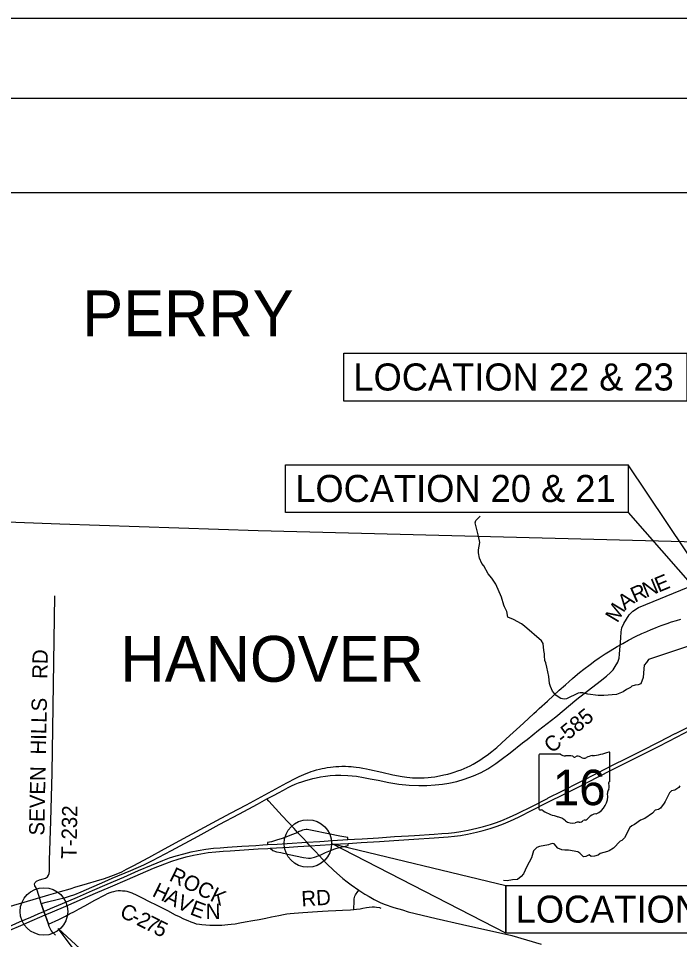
# Model space of a CAD drawing. Extents: x 0 to 34, y 0 to 22.
# Drawn here: x 10.63 to 14.77, y 16.22 to 22 of the extents above; entities that cross this region are included whole.
import ezdxf

# ---------------------------------------------------------------- set-up
doc = ezdxf.new("R2010")
doc.units = 0
for name, color, linetype in [('BR_P_Gen_Text', 7, 'Continuous'), ('Default', 7, 'Continuous'), ('GM_X_County_Road', 7, 'Continuous'), ('GM_X_County_Road_Text', 7, 'Continuous'), ('GM_X_Interchange_Ramps', 7, 'Continuous'), ('GM_X_Minor_River', 7, 'Continuous'), ('GM_X_Rail_Line', 7, 'Continuous'), ('GM_X_State_Route', 7, 'Continuous'), ('GM_X_State_Shield', 7, 'Continuous'), ('GM_X_Township', 7, 'Continuous'), ('GM_X_Township_Road', 7, 'Continuous'), ('GM_X_Township_Road_Text', 7, 'Continuous'), ('GM_X_Township_Text', 7, 'Continuous'), ('SH_Border', 7, 'Continuous'), ('SH_Cut_Line', 7, 'Continuous'), ('SH_Text', 7, 'Continuous')]:
    doc.layers.add(name, color=color, linetype=linetype)

msp = doc.modelspace()

# ---------------------------------------------------------------- linework, layer by layer
at = {"layer": 'BR_P_Gen_Text'}
for points in [[(12.6681, 19.8992), (14.8201, 19.8992), (14.8201, 19.5989), (12.6681, 19.5989)], [(12.3032, 19.1999), (14.4514, 19.1999), (14.4514, 18.8997), (12.3032, 18.8997)], [(14.4514, 19.1999), (14.4514, 18.8997), (15.3028, 17.9312)], [(13.6851, 16.5609), (13.6851, 16.2607), (12.5922, 16.8244)], [(13.6851, 16.5609), (15.8312, 16.5609), (15.8312, 16.2607), (13.6851, 16.2607)], [(11.6138, 15.6114), (11.6138, 15.3112), (10.8775, 16.2902)]]:
    msp.add_lwpolyline(points, close=True, dxfattribs=at)
at = {"layer": 'Default'}
for centre in [(12.4433, 16.8244), (10.7881, 16.398)]:
    msp.add_circle(centre, 0.149, dxfattribs=at)
at = {"layer": 'GM_X_County_Road'}
msp.add_line((10.7963, 16.3759), (10.8163, 16.3184), dxfattribs=at)
for points in [[(11.4683, 16.7168), (11.5872, 16.7801), (11.7557, 16.8707), (11.8872, 16.9424), (12.0134, 17.0104), (12.1272, 17.0718), (12.1864, 17.1037), (12.231, 17.1282), (12.2588, 17.1423), (12.2899, 17.1594), (12.319, 17.1748), (12.3404, 17.185), (12.3639, 17.1957), (12.3852, 17.2043), (12.4049, 17.2111), (12.4296, 17.2192), (12.4529, 17.2261), (12.4732, 17.232), (12.495, 17.2367), (12.5224, 17.242), (12.5531, 17.2469), (12.5823, 17.2502), (12.6156, 17.252), (12.649, 17.253), (12.6947, 17.2516), (12.7489, 17.2462), (12.7921, 17.2389), (12.8343, 17.2304), (12.8836, 17.2205), (12.9513, 17.207), (13.0141, 17.1961), (13.0787, 17.1899), (13.1393, 17.1875), (13.1883, 17.1886), (13.2418, 17.1916), (13.2864, 17.1969), (13.3266, 17.2032), (13.3769, 17.2136), (13.4237, 17.2271), (13.4823, 17.248), (13.5289, 17.2693), (13.5726, 17.2929), (13.6222, 17.3251), (13.6561, 17.3506), (13.7115, 17.3938), (13.7899, 17.4552), (13.8178, 17.4761), (13.8899, 17.5341), (13.998, 17.619), (14.1297, 17.7296), (14.2764, 17.842), (14.3148, 17.8733), (14.3402, 17.8963), (14.3576, 17.914), (14.3705, 17.9335), (14.3858, 17.9627), (14.3942, 17.9878), (14.3976, 18.0121), (14.406, 18.1138), (14.4078, 18.153), (14.4121, 18.1764), (14.4247, 18.2053), (14.4572, 18.2595), (14.4802, 18.2806), (14.5173, 18.3053), (14.8268, 18.432)], [(12.513, 16.7489), (12.49, 16.773), (12.4561, 16.8103), (12.4359, 16.8319), (12.413, 16.8571), (12.3788, 16.8938), (12.3568, 16.9179), (12.2812, 16.9986), (12.1979, 17.0898), (12.1864, 17.1037)], [(10.7699, 16.4471), (10.8105, 16.4578), (10.8709, 16.4731), (10.9224, 16.4864), (10.9479, 16.4933), (10.9818, 16.5046), (11.022, 16.5206), (11.1705, 16.5851), (11.2167, 16.6057), (11.3322, 16.6543), (11.4135, 16.6899), (11.4683, 16.7168)], [(10.8163, 16.3184), (10.8819, 16.3481), (10.9023, 16.3584), (10.9239, 16.369), (10.9485, 16.3827), (10.9788, 16.3986), (11.009, 16.4149), (11.0439, 16.4339), (11.1077, 16.4677), (11.1712, 16.5023), (11.1871, 16.51), (11.2028, 16.5169), (11.2151, 16.5216), (11.2254, 16.5239), (11.2403, 16.5269), (11.2533, 16.5286), (11.2676, 16.5289), (11.2802, 16.5282), (11.2968, 16.5262), (11.3081, 16.5246), (11.3204, 16.5213), (11.339, 16.5149), (11.3703, 16.4997), (11.4048, 16.4824), (11.4477, 16.4604), (11.4919, 16.4388), (11.562, 16.4033), (11.6115, 16.377), (11.6365, 16.3654), (11.6637, 16.3524), (11.691, 16.3401), (11.7086, 16.3325), (11.7272, 16.3255), (11.7431, 16.3212), (11.7631, 16.3175), (11.7787, 16.3162), (11.803, 16.3142), (11.8276, 16.3125), (11.8518, 16.3119), (11.8771, 16.3125), (11.903, 16.3129), (11.9223, 16.3139), (11.9419, 16.3155), (11.9618, 16.3175), (11.9874, 16.3209), (12.017, 16.3258), (12.0502, 16.3318), (12.0971, 16.3408), (12.137, 16.3484), (12.1788, 16.3568), (12.2147, 16.3644), (12.2619, 16.3734), (12.2908, 16.379), (12.3111, 16.3823), (12.3327, 16.3853), (12.3566, 16.388), (12.3835, 16.39), (12.4105, 16.392), (12.5032, 16.397), (12.5341, 16.399), (12.5694, 16.4009), (12.6188, 16.4042), (12.6609, 16.4068), (12.7112, 16.4089), (12.7308, 16.4096), (12.7483, 16.4129), (12.7705, 16.4153), (12.7873, 16.4184), (12.8098, 16.4217), (12.8268, 16.4243), (12.8455, 16.4259), (12.8608, 16.4262), (12.8738, 16.425), (12.8918, 16.4219), (12.9001, 16.4191)], [(12.7308, 16.4096), (12.7325, 16.4638), (12.7334, 16.4772), (12.7349, 16.486), (12.7377, 16.494), (12.7415, 16.5018), (12.7457, 16.5087), (12.7519, 16.5176), (12.762, 16.5318)], [(10.7699, 16.4471), (10.7881, 16.398), (10.7963, 16.3759)]]:
    msp.add_lwpolyline(points, dxfattribs=at)
at = {"layer": 'GM_X_Interchange_Ramps'}
for points in [[(12.3788, 16.8938), (12.3693, 16.8892), (12.341, 16.8778), (12.3145, 16.8672), (12.2819, 16.8564), (12.2473, 16.8452), (12.2145, 16.8356), (12.1899, 16.8307), (12.1907, 16.817)], [(12.6943, 16.8488), (12.6934, 16.8628), (12.6682, 16.8661), (12.6436, 16.8705), (12.5728, 16.8856), (12.4707, 16.9064), (12.449, 16.9103), (12.4395, 16.9112), (12.4322, 16.9112), (12.4204, 16.9097), (12.4099, 16.907), (12.4021, 16.9043), (12.3894, 16.8988), (12.3788, 16.8938)], [(12.513, 16.7489), (12.5277, 16.7553), (12.5529, 16.7673), (12.5844, 16.7799), (12.6129, 16.79), (12.6403, 16.7982), (12.6658, 16.8045), (12.6965, 16.8109), (12.6958, 16.8252)]]:
    msp.add_lwpolyline(points, dxfattribs=at)
at = {"layer": 'GM_X_Minor_River'}
for points in [[(14.8866, 18.0813), (14.58, 17.9789), (14.5673, 17.9596), (14.5526, 17.9435), (14.5489, 17.9198), (14.5459, 17.8648), (14.532, 17.8263), (14.5141, 17.8192), (14.4956, 17.8172), (14.4739, 17.8101), (14.4656, 17.8023), (14.4407, 17.7894), (14.4209, 17.7746), (14.3794, 17.7591), (14.2995, 17.7536), (14.2912, 17.7529), (14.2643, 17.7528), (14.1977, 17.7602), (14.167, 17.7684), (14.1504, 17.7702), (14.1376, 17.7676), (14.0648, 17.7327), (14.0501, 17.7301), (14.0303, 17.7338), (14.0181, 17.7395), (13.9976, 17.7548), (13.9763, 17.779), (13.9641, 17.8091), (13.9576, 17.8289), (13.9542, 17.8724), (13.9425, 17.9312), (13.9353, 17.9574), (13.9282, 17.9721), (13.9275, 18.0022), (13.9261, 18.015), (13.9222, 18.0342), (13.9188, 18.0783), (13.9085, 18.0955), (13.8007, 18.1879), (13.7821, 18.2012), (13.7334, 18.2285), (13.6969, 18.2444), (13.691, 18.2795), (13.6768, 18.3089), (13.6729, 18.3185), (13.6567, 18.3696), (13.6218, 18.4514), (13.5967, 18.489), (13.5729, 18.5152), (13.5465, 18.5656), (13.5349, 18.5809), (13.5201, 18.6148), (13.5129, 18.6474), (13.5122, 18.6659), (13.521, 18.7133), (13.5138, 18.753), (13.493, 18.8367), (13.4961, 18.8508), (13.5235, 18.8785)], [(14.7757, 17.1861), (14.7688, 17.1746), (14.7439, 17.1584), (14.7228, 17.1545), (14.7107, 17.1429), (14.6828, 17.0871), (14.6777, 17.0782), (14.6548, 17.046), (14.6414, 17.0383), (14.6216, 17.0325), (14.6044, 17.0151), (14.5553, 16.981), (14.5291, 16.9706), (14.4915, 16.9429), (14.4755, 16.9352), (14.4615, 16.9236), (14.4278, 16.8588), (14.4126, 16.844), (14.4023, 16.8382), (14.3603, 16.7945), (14.3329, 16.779), (14.3227, 16.7738), (14.276, 16.7608), (14.2626, 16.7518), (14.2396, 16.7453), (14.2192, 16.7433), (14.2063, 16.7522), (14.1853, 16.7425), (14.1706, 16.7412), (14.1494, 16.7635), (14.1359, 16.7724), (14.0783, 16.7823), (14.0546, 16.7822), (14.036, 16.7854), (14.0104, 16.7955), (13.9873, 16.8229), (13.9777, 16.8248), (13.9617, 16.8209), (13.9528, 16.8157), (13.8952, 16.8059), (13.8799, 16.7981), (13.8583, 16.7788), (13.8444, 16.7339), (13.8158, 16.6801), (13.7962, 16.6345), (13.7815, 16.6165), (13.7586, 16.5985), (13.7253, 16.5964), (13.6927, 16.5899), (13.6703, 16.5911)]]:
    msp.add_lwpolyline(points, dxfattribs=at)
at = {"layer": 'GM_X_Rail_Line'}
msp.add_lwpolyline([(10.4028, 16.3818), (10.6648, 16.4571), (10.8196, 16.5024), (10.8928, 16.5235), (10.9516, 16.5407), (10.9882, 16.5519), (11.0402, 16.5667), (11.1391, 16.5956), (11.1622, 16.6026), (11.19, 16.612), (11.2076, 16.6185), (11.2247, 16.6252), (11.2513, 16.6362), (11.276, 16.6474), (11.3059, 16.6622), (11.3479, 16.6847), (11.4456, 16.737), (11.5437, 16.7902), (11.6408, 16.8431), (11.846, 16.9538), (11.9588, 17.0149), (12.0583, 17.0673), (12.1504, 17.1173), (12.3118, 17.2045), (12.3676, 17.2337), (12.3886, 17.2435), (12.4042, 17.251), (12.4178, 17.257), (12.4331, 17.2634), (12.4485, 17.2695), (12.4646, 17.2751), (12.4791, 17.28), (12.4976, 17.2858), (12.5162, 17.2907), (12.5325, 17.2945), (12.5479, 17.2977), (12.5644, 17.3005), (12.5841, 17.3034), (12.601, 17.3056), (12.6175, 17.3067), (12.6375, 17.3081), (12.6567, 17.3089), (12.6799, 17.3087), (12.6989, 17.3082), (12.7147, 17.307), (12.7287, 17.3056), (12.7461, 17.3036), (12.7666, 17.3008), (12.787, 17.2972), (12.811, 17.2926), (12.8294, 17.2891), (12.9076, 17.271), (12.9749, 17.2553), (13.0334, 17.2435), (13.0628, 17.2396), (13.0821, 17.2376), (13.0995, 17.2366), (13.1169, 17.2355), (13.1341, 17.2353), (13.1493, 17.2358), (13.1734, 17.2362), (13.1982, 17.2383), (13.2173, 17.2403), (13.2395, 17.2431), (13.2689, 17.2482), (13.2966, 17.2544), (13.3207, 17.2601), (13.3422, 17.2659), (13.3613, 17.2724), (13.3829, 17.2796), (13.4043, 17.2873), (13.4237, 17.2951), (13.4425, 17.304), (13.4602, 17.3124), (13.4802, 17.3227), (13.5204, 17.346), (13.5363, 17.3565), (13.5514, 17.3668), (13.5673, 17.378), (13.5975, 17.4019), (13.6273, 17.4264), (13.6873, 17.4807), (13.7944, 17.5784), (13.8607, 17.6398), (13.8774, 17.6553), (13.8938, 17.6701), (13.9457, 17.7161), (14.0199, 17.7851), (14.0578, 17.8203), (14.0812, 17.8405), (14.1029, 17.859), (14.1196, 17.8733), (14.147, 17.8969), (14.1728, 17.9171), (14.2123, 17.9469), (14.2435, 17.9698), (14.2696, 17.988), (14.3083, 18.0138), (14.3397, 18.0335), (14.3819, 18.0595), (14.4176, 18.0794), (14.4536, 18.0998), (14.497, 18.1219), (14.5383, 18.1415), (14.5685, 18.1549), (14.5961, 18.1666), (14.6235, 18.1777), (14.6418, 18.1847), (14.6639, 18.1929), (14.696, 18.2048), (14.7241, 18.214), (14.7556, 18.2241), (14.7808, 18.2321)], dxfattribs=at)
at = {"layer": 'GM_X_State_Route'}
for points in [[(10.5653, 16.302), (10.6357, 16.3324), (10.7052, 16.3623), (10.7524, 16.3825), (10.7881, 16.398), (10.8289, 16.4156), (10.9046, 16.4481), (10.998, 16.4883), (11.0922, 16.5291), (11.1848, 16.569), (11.2892, 16.6137), (11.3819, 16.6538), (11.4632, 16.689), (11.5333, 16.7177), (11.5757, 16.7333), (11.618, 16.7467), (11.6661, 16.7602), (11.7105, 16.7711), (11.7557, 16.7803), (11.804, 16.7883), (11.8513, 16.794), (11.8941, 16.798), (11.9395, 16.8013), (12.0285, 16.8068), (12.1161, 16.8124), (12.1611, 16.8152), (12.1907, 16.817), (12.2511, 16.8208), (12.3137, 16.8248), (12.4359, 16.8319), (12.5184, 16.8375), (12.5974, 16.8427), (12.6943, 16.8488), (12.7346, 16.8511), (12.784, 16.8543), (12.8856, 16.8607), (12.9872, 16.8672), (13.0733, 16.8726), (13.1125, 16.875), (13.2358, 16.883), (13.2841, 16.8861), (13.3244, 16.8894), (13.3623, 16.8937), (13.402, 16.8992), (13.4482, 16.9074), (13.5024, 16.9196), (13.5446, 16.9306), (13.5883, 16.9437), (13.6262, 16.9567), (13.6594, 16.969), (13.7084, 16.9893), (13.7534, 17.0104), (13.855, 17.0613), (13.9459, 17.1073), (13.9503, 17.1096), (14.0366, 17.1535), (14.1499, 17.211), (14.2619, 17.2679), (14.3543, 17.3147), (14.4432, 17.3595), (14.5347, 17.4057), (14.646, 17.4627), (14.7453, 17.5132), (14.7488, 17.515), (14.8404, 17.561)], [(12.5844, 16.8182), (12.5988, 16.8191), (12.6958, 16.8252), (12.7776, 16.8305), (12.8917, 16.8377), (12.9813, 16.8431), (13.108, 16.8513), (13.235, 16.8594), (13.3238, 16.8656), (13.3616, 16.8695), (13.3992, 16.8748), (13.4434, 16.8824), (13.4997, 16.8943), (13.5421, 16.9053), (13.5864, 16.9182), (13.6304, 16.933), (13.6704, 16.9476), (13.7134, 16.9659), (13.7638, 16.9892), (13.8548, 17.0351), (13.9447, 17.0807), (14.0583, 17.1383), (14.1621, 17.191), (14.2541, 17.2372), (14.3585, 17.2903), (14.4493, 17.3363), (14.5411, 17.3828), (14.645, 17.4358), (14.7589, 17.4939), (14.8391, 17.5341)], [(12.3794, 16.8055), (12.4561, 16.8103), (12.5844, 16.8182)], [(10.5742, 16.2801), (10.6438, 16.3104), (10.7142, 16.3404), (10.762, 16.3611), (10.7963, 16.3759), (10.8422, 16.3956), (10.9248, 16.4313), (11.0291, 16.4763), (11.1122, 16.5119), (11.2054, 16.5522), (11.3113, 16.5981), (11.3932, 16.633), (11.4753, 16.6687), (11.5466, 16.6975), (11.5895, 16.7134), (11.6308, 16.7265), (11.6798, 16.7401), (11.726, 16.7509), (11.7725, 16.7602), (11.8179, 16.7668), (11.8665, 16.7723), (11.9118, 16.7761), (11.9553, 16.7788), (12.0443, 16.7843), (12.1319, 16.7899), (12.1919, 16.7936), (12.2064, 16.7945)], [(12.2064, 16.7945), (12.3257, 16.8021), (12.3794, 16.8055)], [(12.2064, 16.7945), (12.2233, 16.7802), (12.2471, 16.7724), (12.2734, 16.7667), (12.326, 16.7558), (12.4158, 16.7372), (12.4477, 16.7324), (12.4586, 16.7323), (12.4686, 16.7337), (12.4855, 16.7385), (12.513, 16.7489)], [(12.513, 16.7489), (12.534, 16.7258), (12.5617, 16.6963), (12.6044, 16.6563), (12.6621, 16.6051), (12.6892, 16.5845), (12.7155, 16.5644), (12.762, 16.5318), (12.8006, 16.5072), (12.8275, 16.4914), (12.8594, 16.4737), (12.897, 16.455), (12.9213, 16.4439), (12.9823, 16.4236), (13.0365, 16.408), (13.071, 16.3947), (13.2481, 16.3542), (13.4119, 16.3157), (13.7225, 16.2469), (13.9067, 16.1931)]]:
    msp.add_lwpolyline(points, dxfattribs=at)
at = {"layer": 'GM_X_State_Shield'}
for p, q in [((13.8922, 17.3785), (13.8922, 17.0408)), ((14.0269, 17.3843), (13.8966, 17.3843)), ((14.3371, 17.216), (14.3371, 17.3926)), ((14.3371, 17.216), (14.3371, 17.216))]:
    msp.add_line(p, q, dxfattribs=at)
for centre, radius, start, end in [((14.1786, 17.8447), 0.4719, 275.84447, 288.90645), ((14.3322, 17.3934), 0.00495, 351.86209, 97.738), ((13.8973, 17.3792), 0.00515, 98.1301, 188.1301), ((14.0579, 17.4235), 0.05, 231.61951, 271.11188), ((14.0745, 17.1947), 0.1795, 80.48669, 94.98827), ((14.1152, 17.3809), 0.0144, 219.79206, 297.10237), ((14.1364, 17.3419), 0.03, 54.46668, 119.14113), ((14.1751, 17.3954), 0.0361, 233.85621, 294.82819), ((14.2388, 17.2811), 0.0949, 97.34618, 120.76885), ((14.3549, 17.1421), 0.0335, 136.8065, 186.92959), ((14.336, 17.203), 0.00767, 107.94398, 210.33697), ((14.2872, 17.1807), 0.046, 340.03296, 23.64957), ((14.3318, 17.2153), 0.0053, 289.60381, 7.73413), ((14.2051, 17.1196), 0.118, 292.30889, 8.98584), ((13.8973, 17.04), 0.0052, 171.95839, 258.30661), ((13.8981, 17.0746), 0.0397, 267.33899, 280.60386), ((13.9062, 17.0213), 0.0143, 29.74838, 93.27175), ((14.0869, 17.3247), 0.3407, 240.41292, 257.1985), ((13.9853, 16.889), 0.1066, 47.18416, 75.83597), ((14.2548, 16.9459), 0.0646, 94.40312, 142.57675), ((14.1006, 17.0196), 0.0677, 230.70037, 286.29184), ((14.1397, 16.9028), 0.0556, 85.69512, 111.20995), ((14.1446, 16.9943), 0.036, 268.77702, 315.54927), ((14.1773, 16.9616), 0.0101, 65.75173, 132.64842), ((14.1729, 17.008), 0.0381, 282.87319, 323.27711)]:
    msp.add_arc(centre, radius, start, end, dxfattribs=at)
at = {"layer": 'GM_X_Township'}
msp.add_lwpolyline([(7.2878, 13.067), (7.3449, 14.3381), (7.3457, 14.3583), (7.3798, 15.3309), (7.3804, 15.3492), (7.3808, 15.3569), (7.3817, 15.3787), (7.3819, 15.3847), (7.4355, 16.6384), (7.5303, 18.6845), (7.5438, 18.9496), (8.5619, 18.9174), (10.8875, 18.8291), (12.1312, 18.787), (15.1269, 18.7101), (15.5418, 18.6967), (15.9755, 18.686)], dxfattribs=at)
at = {"layer": 'GM_X_Township_Road'}
msp.add_line((10.8163, 16.3184), (10.7963, 16.3759), dxfattribs=at)
for points in [[(10.7525, 16.5107), (10.7483, 16.5246), (10.7388, 16.5455), (10.7304, 16.5583), (10.7289, 16.5704), (10.7324, 16.5798), (10.7422, 16.588), (10.7605, 16.5963), (10.7822, 16.6021), (10.7978, 16.6075), (10.8099, 16.6159), (10.817, 16.6255), (10.821, 16.6358), (10.8223, 16.6515), (10.8238, 16.7193), (10.8312, 16.9646), (10.84, 17.2673), (10.8569, 18.3786)], [(10.7699, 16.4471), (10.7598, 16.486), (10.7525, 16.5107)], [(10.7963, 16.3759), (10.7881, 16.398), (10.7699, 16.4471)], [(10.8613, 16.2496), (10.8434, 16.2659), (10.8342, 16.2775), (10.8291, 16.2861), (10.8246, 16.2946), (10.8214, 16.3031), (10.8163, 16.3184)]]:
    msp.add_lwpolyline(points, dxfattribs=at)
at = {"layer": 'SH_Border'}
msp.add_lwpolyline([(1.5, 21.5), (33.5, 21.5), (33.5, 0.5), (1.5, 0.5)], close=True, dxfattribs=at)
at = {"layer": 'SH_Cut_Line'}
msp.add_lwpolyline([(0, 0), (34, 0), (34, 22), (0, 22)], close=True, dxfattribs=at)
at = {"layer": 'SH_Text'}
msp.add_lwpolyline([(1.9289, 20.907), (19.068, 20.907), (19.068, 13.067), (1.9289, 13.067)], close=True, dxfattribs=at)

# ---------------------------------------------------------------- texts
at = {"layer": 'BR_P_Gen_Text'}
for s, p in [('LOCATION 22 & 23', (12.7288, 19.6658)), ('LOCATION 20 & 21', (12.364, 18.9665)), ('LOCATION 18 & 19', (13.7459, 16.3275))]:
    msp.add_text(s, height=0.17, dxfattribs=at).set_placement(p)
at = {"layer": 'GM_X_County_Road_Text'}
for s, height, rotation, p in [('E', 0.0959, 22.28689, (14.6424, 18.3976)), ('R', 0.0959, 23.88997, (14.493, 18.3339)), ('N', 0.0959, 22.30603, (14.5644, 18.3655)), ('A', 0.0959, 37.51395, (14.4313, 18.2856)), ('M', 0.0959, 59.0028, (14.384, 18.2035)), ('C-585', 0.09588, 38.96359, (13.9721, 17.3863)), ('ROCK', 0.09588, 333.90411, (11.5675, 16.5941)), ('H', 0.0959, 333.90411, (11.4616, 16.4968)), ('A', 0.0959, 333.90091, (11.5374, 16.4597)), ('RD', 0.09588, 3.48332, (12.4049, 16.4293)), ('V', 0.0959, 333.96262, (11.6132, 16.4225)), ('C', 0.0959, 335.70819, (11.2572, 16.3659)), ('E', 0.0959, 339.48929, (11.6983, 16.3815)), ('N', 0.0959, 0.39974, (11.8029, 16.3497)), ('-', 0.0959, 333.68628, (11.3281, 16.3339)), ('2', 0.0959, 333.39771, (11.3633, 16.3165)), ('7', 0.0959, 333.28599, (11.4161, 16.2901)), ('5', 0.0959, 333.2767, (11.4688, 16.2635))]:
    msp.add_text(s, height=height, rotation=rotation, dxfattribs=at).set_placement(p)
at = {"layer": 'GM_X_State_Shield'}
msp.add_text('16', height=0.22247, dxfattribs=at).set_placement((13.9791, 17.0646))
at = {"layer": 'GM_X_Township_Road_Text'}
for s, rotation, p in [('RD', 89.01278, (10.81, 17.8562)), ('HILLS', 88.83624, (10.8001, 17.3811)), ('SEVEN', 88.93572, (10.7903, 16.8733)), ('T-232', 88.87732, (10.9916, 16.7273))]:
    msp.add_text(s, height=0.09588, rotation=rotation, dxfattribs=at).set_placement(p)
at = {"layer": 'GM_X_Township_Text'}
for s, p in [('PERRY', (11.0284, 20.0064)), ('HANOVER', (11.2676, 17.8388))]:
    msp.add_text(s, height=0.28764, rotation=0.00001, dxfattribs=at).set_placement(p)

doc.saveas('drawing.dxf')
